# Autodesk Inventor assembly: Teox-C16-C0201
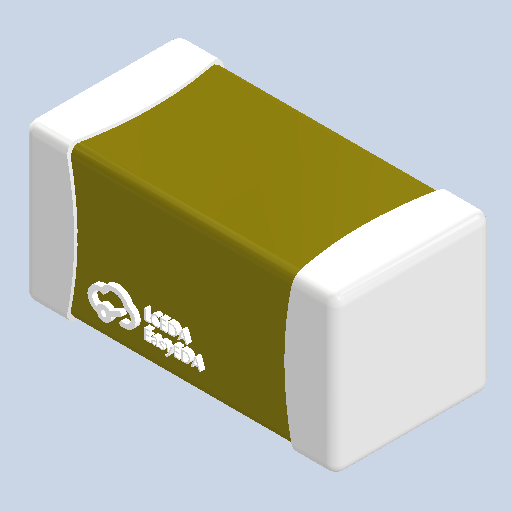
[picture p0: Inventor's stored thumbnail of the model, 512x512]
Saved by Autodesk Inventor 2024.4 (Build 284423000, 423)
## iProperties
Created: 2025-05
Part Number: Teox-C16-C0201
Document SubType Name: Assembly
Designer: AdminForWorker
Title: Teox-C16-C0201
Author: AdminForWorker
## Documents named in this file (2)
- c:\worker\convert-fusion-r02-cosv3\tmp\job-1\2\temp\files\be827049-a7f2-47ea-a815-8d9efd6bfce9\Teox-C16-C0201.iam
- c:\worker\convert-fusion-r02-cosv3\tmp\job-1\2\temp\files\be827049-a7f2-47ea-a815-8d9efd6bfce9\COMPOUND (3).ipt
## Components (1 placed, 1 different names)
1. COMPOUND (3):5
